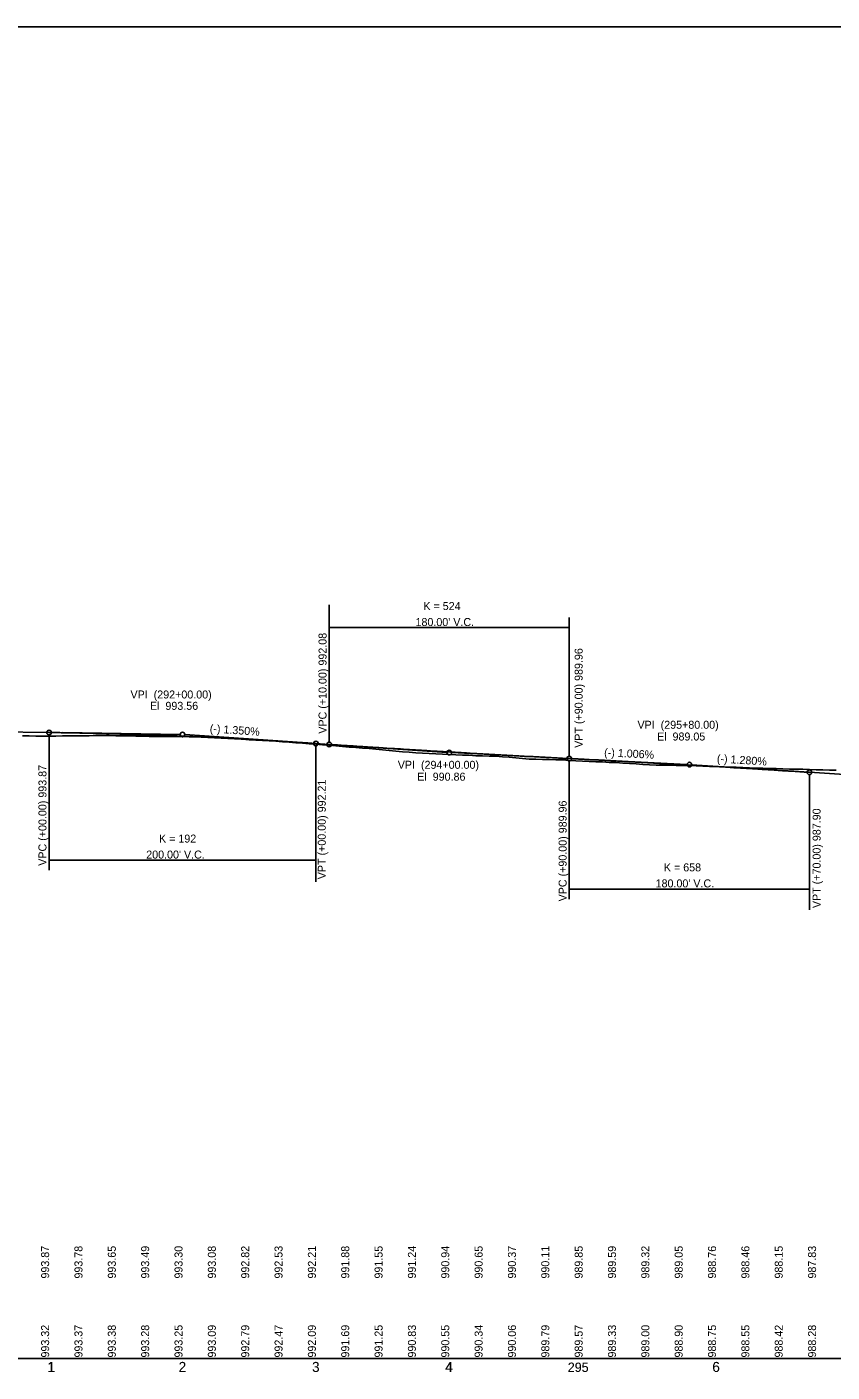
# Model space of a CAD drawing. Extents: x 1608361 to 16979326, y 1092015 to 12565288.
# Drawn here: x 16978069 to 16978673, y 12564278 to 12565286 of the extents above; entities that cross this region are included whole.
import ezdxf

# ---------------------------------------------------------------- set-up
doc = ezdxf.new("R2010")
doc.units = 0
for name, color, linetype in [('Default', 7, 'Continuous'), ('points EP', 7, 'Continuous'), ('RD_EX_Fence_ChLk', 7, 'Continuous'), ('RD_EX_H2O', 7, 'Continuous'), ('RD_EX_RW_Approx', 7, 'Continuous'), ('RD_EX_SU_Water', 7, 'Continuous'), ('RD_EX_UT', 7, 'Continuous'), ('RD_HC_TX_Rel_Sta50', 7, 'Continuous'), ('RD_PD_Final_TX', 7, 'Continuous'), ('TEXT2', 7, 'Continuous')]:
    doc.layers.add(name, color=color, linetype=linetype)

msp = doc.modelspace()

# ---------------------------------------------------------------- linework, layer by layer
at = {"layer": 'Default'}
msp.add_lwpolyline([(16977485.6, 12564287.8), (16978985.6, 12564287.8), (16978985.6, 12565286), (16977485.6, 12565286)], close=True, dxfattribs=at)
at = {"layer": 'RD_EX_Fence_ChLk'}
for p, q in [((16978295.6, 12564852.7), (16978295.6, 12564749.9)), ((16978475.6, 12564843.2), (16978475.6, 12564739.3)), ((16978295.6, 12564835.7), (16978475.6, 12564835.7)), ((16978085.6, 12564653.8), (16978085.6, 12564755.4)), ((16978285.6, 12564645.1), (16978285.6, 12564747.1)), ((16978475.6, 12564632.3), (16978475.6, 12564735.8)), ((16978655.6, 12564624.1), (16978655.6, 12564725.5)), ((16978085.6, 12564661.3), (16978285.6, 12564661.3)), ((16978475.6, 12564639.8), (16978655.6, 12564639.8))]:
    msp.add_line(p, q, dxfattribs=at)
for centre in [(16978085.6, 12564757.1), (16978285.6, 12564748.8), (16978295.6, 12564748.2), (16978475.6, 12564737.6), (16978475.6, 12564737.6), (16978655.6, 12564727.3)]:
    msp.add_circle(centre, 1.75, dxfattribs=at)
at = {"layer": 'RD_EX_H2O'}
for points in [[(16978065.6, 12564754.5), (16978070.6, 12564754.5), (16978075.6, 12564754.4), (16978080.6, 12564754.4), (16978085.6, 12564754.4), (16978090.6, 12564754.4), (16978095.6, 12564754.5), (16978100.6, 12564754.6), (16978105.6, 12564754.6), (16978110.6, 12564754.7), (16978115.6, 12564754.7), (16978120.6, 12564754.8), (16978125.6, 12564754.8), (16978130.6, 12564754.8), (16978135.6, 12564754.7), (16978140.6, 12564754.7), (16978145.6, 12564754.5), (16978150.6, 12564754.4), (16978155.6, 12564754.3), (16978160.6, 12564754.2), (16978165.6, 12564754.2), (16978170.6, 12564754.2), (16978175.6, 12564754.2), (16978180.6, 12564754.1), (16978185.6, 12564754), (16978190.6, 12564753.9), (16978195.6, 12564753.8), (16978200.6, 12564753.6), (16978205.6, 12564753.4), (16978210.6, 12564753.2), (16978215.6, 12564753), (16978220.6, 12564752.6), (16978225.6, 12564752.3), (16978230.6, 12564752), (16978235.6, 12564751.7), (16978240.6, 12564751.4), (16978245.6, 12564751.1), (16978250.6, 12564750.8), (16978255.6, 12564750.5), (16978260.6, 12564750.1), (16978265.6, 12564749.8), (16978270.6, 12564749.4), (16978275.6, 12564749), (16978280.6, 12564748.6), (16978285.6, 12564748.3), (16978290.6, 12564747.9), (16978295.6, 12564747.5), (16978300.6, 12564747.1), (16978305.6, 12564746.7), (16978310.6, 12564746.2), (16978315.6, 12564745.8), (16978320.6, 12564745.4), (16978325.6, 12564745), (16978330.6, 12564744.5), (16978335.6, 12564744), (16978340.6, 12564743.6), (16978345.6, 12564743.1), (16978350.6, 12564742.7), (16978355.6, 12564742.4), (16978360.6, 12564741.9), (16978365.6, 12564741.5), (16978370.6, 12564741.3), (16978375.6, 12564741), (16978380.6, 12564740.8), (16978385.6, 12564740.5), (16978390.6, 12564740.3), (16978395.6, 12564740.2), (16978400.6, 12564740), (16978405.6, 12564739.7), (16978410.6, 12564739.5), (16978415.6, 12564739.4), (16978420.6, 12564739.3), (16978425.6, 12564738.9), (16978430.6, 12564738.5), (16978435.6, 12564738.1), (16978440.6, 12564737.6), (16978445.6, 12564737.2), (16978450.6, 12564737.1), (16978455.6, 12564736.9), (16978460.6, 12564736.8), (16978465.6, 12564736.7), (16978470.6, 12564736.5), (16978475.6, 12564736.2), (16978480.6, 12564735.9), (16978485.6, 12564735.7)], [(16978485.6, 12564735.7), (16978490.6, 12564735.4), (16978495.6, 12564735.2), (16978500.6, 12564735), (16978505.6, 12564734.7), (16978510.6, 12564734.5), (16978515.6, 12564734.2), (16978520.6, 12564733.9), (16978525.6, 12564733.5), (16978530.6, 12564733.1), (16978535.6, 12564732.8), (16978540.6, 12564732.7), (16978545.6, 12564732.6), (16978550.6, 12564732.5), (16978555.6, 12564732.3), (16978560.6, 12564732.3), (16978565.6, 12564732.3), (16978570.6, 12564732.1), (16978575.6, 12564731.9), (16978580.6, 12564731.7), (16978585.6, 12564731.5), (16978590.6, 12564731.3), (16978595.6, 12564731), (16978600.6, 12564731), (16978605.6, 12564730.8), (16978610.6, 12564730.5), (16978615.6, 12564730.4), (16978620.6, 12564730.3), (16978625.6, 12564730.1), (16978630.6, 12564730), (16978635.6, 12564729.9), (16978640.6, 12564729.7), (16978645.6, 12564729.6), (16978650.6, 12564729.5), (16978655.6, 12564729.3), (16978660.6, 12564729.2), (16978665.6, 12564729.1), (16978670.6, 12564728.9), (16978675.6, 12564728.8)]]:
    msp.add_lwpolyline(points, dxfattribs=at)
at = {"layer": 'RD_EX_RW_Approx'}
for p, q in [((16978095.6, 12564757), (16978183.8, 12564755.6)), ((16978275.4, 12564749.5), (16978187.3, 12564755.5)), ((16978295.8, 12564748.2), (16978383.8, 12564742.2)), ((16978475.4, 12564737.6), (16978387.3, 12564742)), ((16978475.7, 12564737.6), (16978563.8, 12564733.1)), ((16978655.4, 12564727.3), (16978567.3, 12564732.9))]:
    msp.add_line(p, q, dxfattribs=at)
for centre in [(16978185.6, 12564755.6), (16978385.6, 12564742.1), (16978565.6, 12564733)]:
    msp.add_circle(centre, 1.75, dxfattribs=at)
at = {"layer": 'RD_EX_UT'}
msp.add_line((16972985.6, 12564287.8), (16978789.9, 12564287.8), dxfattribs=at)
at = {"layer": 'RD_HC_TX_Rel_Sta50'}
for p, q in [((16977995.6, 12564758.5), (16978085.6, 12564757.1)), ((16978285.6, 12564748.8), (16978295.6, 12564748.2)), ((16978655.6, 12564727.3), (16978685.6, 12564725.4))]:
    msp.add_line(p, q, dxfattribs=at)
for points in [[(16978085.6, 12564757.1), (16978089.6, 12564757.1), (16978093.6, 12564757), (16978097.6, 12564756.9), (16978101.6, 12564756.9), (16978105.6, 12564756.8), (16978109.6, 12564756.7), (16978113.6, 12564756.6), (16978117.6, 12564756.5), (16978121.6, 12564756.4), (16978125.6, 12564756.3), (16978129.6, 12564756.2), (16978133.6, 12564756.1), (16978137.6, 12564756), (16978141.6, 12564755.9), (16978145.6, 12564755.7), (16978149.6, 12564755.6), (16978153.6, 12564755.5), (16978157.6, 12564755.3), (16978161.6, 12564755.2), (16978165.6, 12564755.1), (16978169.6, 12564754.9), (16978173.6, 12564754.8), (16978177.6, 12564754.6), (16978181.6, 12564754.5), (16978185.6, 12564754.3), (16978189.6, 12564754.1), (16978193.6, 12564754), (16978197.6, 12564753.8), (16978201.6, 12564753.6), (16978205.6, 12564753.4), (16978209.6, 12564753.2), (16978213.6, 12564753), (16978217.6, 12564752.8), (16978221.6, 12564752.6), (16978225.6, 12564752.4), (16978229.6, 12564752.2), (16978233.6, 12564752), (16978237.6, 12564751.8), (16978241.6, 12564751.6), (16978245.6, 12564751.3), (16978249.6, 12564751.1), (16978253.6, 12564750.9), (16978257.6, 12564750.6), (16978261.6, 12564750.4), (16978265.6, 12564750.1), (16978269.6, 12564749.9), (16978273.6, 12564749.6), (16978277.6, 12564749.4), (16978281.6, 12564749.1), (16978285.6, 12564748.8)], [(16978295.6, 12564748.2), (16978299.2, 12564747.9), (16978302.8, 12564747.7), (16978306.4, 12564747.4), (16978310, 12564747.2), (16978313.6, 12564747), (16978317.2, 12564746.7), (16978320.8, 12564746.5), (16978324.4, 12564746.3), (16978328, 12564746), (16978331.6, 12564745.8), (16978335.2, 12564745.6), (16978338.8, 12564745.3), (16978342.4, 12564745.1), (16978346, 12564744.9), (16978349.6, 12564744.7), (16978353.2, 12564744.4), (16978356.8, 12564744.2), (16978360.4, 12564744), (16978364, 12564743.8), (16978367.6, 12564743.6), (16978371.2, 12564743.3), (16978374.8, 12564743.1), (16978378.4, 12564742.9), (16978382, 12564742.7), (16978385.6, 12564742.5), (16978389.2, 12564742.3), (16978392.8, 12564742.1), (16978396.4, 12564741.9), (16978400, 12564741.6), (16978403.6, 12564741.4), (16978407.2, 12564741.2), (16978410.8, 12564741), (16978414.4, 12564740.8), (16978418, 12564740.6), (16978421.6, 12564740.4), (16978425.2, 12564740.2), (16978428.8, 12564740), (16978432.4, 12564739.8), (16978436, 12564739.6), (16978439.6, 12564739.4), (16978443.2, 12564739.2), (16978446.8, 12564739.1), (16978450.4, 12564738.9), (16978454, 12564738.7), (16978457.6, 12564738.5), (16978461.2, 12564738.3), (16978464.8, 12564738.1), (16978468.4, 12564737.9), (16978472, 12564737.7), (16978475.6, 12564737.6)], [(16978475.6, 12564737.6), (16978479.2, 12564737.4), (16978482.8, 12564737.2), (16978486.4, 12564737), (16978490, 12564736.8), (16978493.6, 12564736.6), (16978497.2, 12564736.5), (16978500.8, 12564736.3), (16978504.4, 12564736.1), (16978508, 12564735.9), (16978511.6, 12564735.7), (16978515.2, 12564735.5), (16978518.8, 12564735.3), (16978522.4, 12564735.1), (16978526, 12564734.9), (16978529.6, 12564734.7), (16978533.2, 12564734.5), (16978536.8, 12564734.3), (16978540.4, 12564734.1), (16978544, 12564733.9), (16978547.6, 12564733.7), (16978551.2, 12564733.5), (16978554.8, 12564733.3), (16978558.4, 12564733.1), (16978562, 12564732.9), (16978565.6, 12564732.7), (16978569.2, 12564732.5), (16978572.8, 12564732.3), (16978576.4, 12564732.1), (16978580, 12564731.9), (16978583.6, 12564731.7), (16978587.2, 12564731.5), (16978590.8, 12564731.3), (16978594.4, 12564731.1), (16978598, 12564730.8), (16978601.6, 12564730.6), (16978605.2, 12564730.4), (16978608.8, 12564730.2), (16978612.4, 12564730), (16978616, 12564729.8), (16978619.6, 12564729.5), (16978623.2, 12564729.3), (16978626.8, 12564729.1), (16978630.4, 12564728.9), (16978634, 12564728.6), (16978637.6, 12564728.4), (16978641.2, 12564728.2), (16978644.8, 12564728), (16978648.4, 12564727.7), (16978652, 12564727.5), (16978655.6, 12564727.3)]]:
    msp.add_spline(points, degree=3, dxfattribs=at)

# ---------------------------------------------------------------- texts
at = {"layer": 'points EP'}
for s, rotation, p in [('(-) 1.350%', 356.1384, (16978205.9, 12564757.2)), ('(-) 1.006%', 357.1192, (16978501.6, 12564739.3)), ('(-) 1.280%', 356.3381, (16978586.1, 12564734.7))]:
    msp.add_text(s, height=6, rotation=rotation, dxfattribs=at).set_placement(p)
at = {"layer": 'RD_EX_Fence_ChLk'}
for s, p in [('K = 524', (16978366.2, 12564848.9)), ("180.00' V.C.", (16978360.3, 12564836.9)), ('K = 192', (16978168, 12564674.6)), ("200.00' V.C.", (16978158.4, 12564662.6)), ('K = 658', (16978546.5, 12564653)), ("180.00' V.C.", (16978540.3, 12564641))]:
    msp.add_text(s, height=6, dxfattribs=at).set_placement(p)
for s, p in [('VPC (+10.00) 992.08', (16978293.6, 12564756.2)), ('VPT (+90.00) 989.96', (16978485.6, 12564745.6)), ('VPC (+00.00) 993.87', (16978083.6, 12564657.2)), ('VPT (+00.00) 992.21', (16978293, 12564647.1)), ('VPC (+90.00) 989.96', (16978473.6, 12564630.5)), ('VPT (+70.00) 987.90', (16978664, 12564625.5))]:
    msp.add_text(s, height=6, rotation=90, dxfattribs=at).set_placement(p)
at = {"layer": 'RD_EX_RW_Approx'}
for s, p in [('VPI  (292+00.00)', (16978146.6, 12564782.6)), ('El  993.56', (16978161.2, 12564774.1)), ('VPI  (295+80.00)', (16978526.7, 12564759.9)), ('El  989.05', (16978541.4, 12564751.1)), ('VPI  (294+00.00)', (16978347, 12564729.9)), ('El  990.86', (16978361.6, 12564721))]:
    msp.add_text(s, height=6, dxfattribs=at).set_placement(p)
at = {"layer": 'RD_EX_SU_Water'}
for s, p in [('993.87', (16978085.6, 12564347.8)), ('993.78', (16978110.6, 12564347.8)), ('993.65', (16978135.6, 12564347.8)), ('993.49', (16978160.6, 12564347.8)), ('993.30', (16978185.6, 12564347.8)), ('993.08', (16978210.6, 12564347.8)), ('992.82', (16978235.6, 12564347.8)), ('992.53', (16978260.6, 12564347.8)), ('992.21', (16978285.6, 12564347.8)), ('991.88', (16978310.6, 12564347.8)), ('991.55', (16978335.6, 12564347.8)), ('991.24', (16978360.6, 12564347.8)), ('990.94', (16978385.6, 12564347.8)), ('990.65', (16978410.6, 12564347.8)), ('990.37', (16978435.6, 12564347.8)), ('990.11', (16978460.6, 12564347.8)), ('989.85', (16978485.6, 12564347.8)), ('989.59', (16978510.6, 12564347.8)), ('989.32', (16978535.6, 12564347.8)), ('989.05', (16978560.6, 12564347.8)), ('988.76', (16978585.6, 12564347.8)), ('988.46', (16978610.6, 12564347.8)), ('988.15', (16978635.6, 12564347.8)), ('987.83', (16978660.6, 12564347.8))]:
    msp.add_text(s, height=6, rotation=90, dxfattribs=at).set_placement(p)
at = {"layer": 'RD_PD_Final_TX'}
for s, height, p in [('1', 7.5, (16978084.2, 12564277.8)), ('1', 7.5, (16978084.6, 12564277.8)), ('2', 7.5, (16978182.7, 12564277.8)), ('2', 7.5, (16978182.8, 12564277.8)), ('3', 7.5, (16978282.7, 12564277.8)), ('3', 7.5, (16978282.8, 12564277.8)), ('4', 7.5, (16978382.5, 12564277.8)), ('4', 7.5, (16978382.8, 12564277.8)), ('295', 7, (16978474.5, 12564277.8)), ('295', 7, (16978474.4, 12564277.8)), ('6', 7.5, (16978582.8, 12564277.8)), ('6', 7.5, (16978582.9, 12564277.8))]:
    msp.add_text(s, height=height, dxfattribs=at).set_placement(p)
at = {"layer": 'TEXT2'}
for s, p in [('993.32', (16978085.6, 12564288.6)), ('993.37', (16978110.6, 12564288.6)), ('993.38', (16978135.6, 12564288.6)), ('993.28', (16978160.6, 12564288.6)), ('993.25', (16978185.6, 12564288.6)), ('993.09', (16978210.6, 12564288.6)), ('992.79', (16978235.6, 12564288.6)), ('992.47', (16978260.6, 12564288.6)), ('992.09', (16978285.6, 12564288.6)), ('991.69', (16978310.6, 12564288.6)), ('991.25', (16978335.6, 12564288.6)), ('990.83', (16978360.6, 12564288.6)), ('990.55', (16978385.6, 12564288.6)), ('990.34', (16978410.6, 12564288.6)), ('990.06', (16978435.6, 12564288.6)), ('989.79', (16978460.6, 12564288.6)), ('989.57', (16978485.6, 12564288.6)), ('989.33', (16978510.6, 12564288.6)), ('989.00', (16978535.6, 12564288.6)), ('988.90', (16978560.6, 12564288.6)), ('988.75', (16978585.6, 12564288.6)), ('988.55', (16978610.6, 12564288.6)), ('988.42', (16978635.6, 12564288.6)), ('988.28', (16978660.6, 12564288.6))]:
    msp.add_text(s, height=6, rotation=90, dxfattribs=at).set_placement(p)

doc.saveas('drawing.dxf')
